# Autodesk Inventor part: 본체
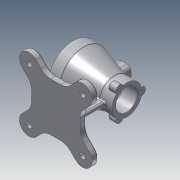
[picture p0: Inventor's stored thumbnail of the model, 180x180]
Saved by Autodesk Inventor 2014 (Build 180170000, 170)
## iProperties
Created: 2018-03
Part Number: 본체
Material: 알루미늄 6061
Document SubType Name: Modeling
Designer: net
Density: 2.71 g/cm^3
Appearance: 알루미늄 - 평지
Mass: 1015 g
Surface Area: 853.881 cm^2
Volume: 374.54 cm^3
Author: net
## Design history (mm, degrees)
sketch "스케치1"
  geometry: L1 (0, 0)-(0, 45); L2 (0, 45)-(20, 45); L3 (0, 0)-(100, 0); L4 (100, 0)-(100, 27.5); L5 (100, 27.5)-(77, 27.5); L6 (20, 45)-(77, 27.5)
  constraints: 12 end point, 2 perpendicular, 1 parallel, 1 vertical
  dimensions: "d0" = 45 distance of L1.start L1.end; "d1" = 20 distance of L1.end L2.end; "d3" = 100 distance of L1.start L3.end; "d4" = 27.5 distance of L3.end L4.end; "d5" = 23 distance of L4.end L5.end
revolve "회전1" sketch "스케치1" stored, may be unused: angle "d6" = 90 deg
sketch "스케치5"
  geometry: L1 (0, 0)-(50, 0); L2 (50, 0)-(50, 45); L3 (50, 45)-(62.5, 45); L4 (62.5, 45)-(62.5, 20); L5 (62.5, 20)-(50, 20); L6 (50, 20)-(50, 45); L7 (62.5, 20)-(37.5, 20); L8 (37.5, 20)-(37.5, 45); L9 (37.5, 45)-(62.5, 45); L10 (62.5, 45)-(62.5, 20)
  constraints: 20 end point, 4 parallel, 3 horizontal, 3 perpendicular
  dimensions: "d16" = 50 distance of L1.start L1.end; "d17" = 45 distance of L1.end L2.end; "d20" = 12.5 distance of L4.end L5.end; "d21" = 25 distance of L3.end L4.end; "d22" = 25 distance of L8.end L9.end
extrude "돌출4" join sketch "스케치5" stored distance "d23" = 25; taper "d24" = 0 deg
sketch "스케치2"
  geometry: C1 r 45 at (0, 0) reference; C2 r 35 at (0, 0)
  constraints: 1 centre point, 1 coincident
  dimensions: "d7" = 35 radius of C2
extrude "돌출1" cut sketch "스케치2" distance "d8" = 23; taper "d9" = 0 deg
sketch "스케치3"
  geometry: C1 r 35 at (0, 0) reference; C2 r 26 at (0, 0)
  constraints: 1 centre point, 1 coincident
  dimensions: "d10" = 26 radius of C2
extrude "돌출2" cut sketch "스케치3" distance "d11" = 47; taper "d12" = 0 deg
sketch "스케치4"
  geometry: C1 r 27.5 at (0, 0) reference; C2 r 20 at (0, 0)
  constraints: 1 centre point, 1 coincident
  dimensions: "d13" = 20 radius of C2
extrude "돌출3" cut sketch "스케치4" distance "d14" = 30; taper "d15" = 0 deg
sketch "스케치6"
  geometry: L1 (0, 25)-(25, 25); L2 (25, 25)-(25, 0); L3 (25, 0)-(0, 0); L4 (0, 0)-(0, 25); L5 (12.5, 12.5)-(20, 12.5); L6 (20, 12.5)-(20, 20); L7 (20, 20)-(12.5, 20); L8 (12.5, 20)-(12.5, 12.5); L9 (20, 20)-(5, 20); L10 (5, 20)-(5, 5); L11 (5, 5)-(20, 5); L12 (20, 5)-(20, 20); 1 further point
  constraints: 24 end point, 6 parallel, 3 horizontal, 3 perpendicular
  dimensions: "d25" = 7.5 distance of L7.end L6.end; "d26" = 7.5 distance of L6.end L5.end; "d27" = 15 distance of L11.end L10.end; "d28" = 15 distance of L10.end L9.end
extrude "돌출5" cut sketch "스케치6" distance "d29" = 30; taper "d30" = 0 deg
sketch "스케치7"
  geometry: L1 (0, 0)-(68.836, -39.743); L2 (0, 0)-(79.485, 0); L3 (0, 0)-(-52.99, -30.594); L4 (0, 0)-(61.188, 0); C1 r 7 at (0, 27.5); C2 r 20 at (0, 0) reference; 1 further point
  constraints: 8 end point, 2 equal length, 2 horizontal, 1 centre point, 1 vertical alignment, 1 other
  dimensions: "d31" = 7 radius of C1; "d116" = 30 deg angle of L1 L2; "d117" = 150 deg angle of L3 L4
extrude "돌출6" join sketch "스케치7" distance "d32" = 15; taper "d33" = 0 deg
sketch "스케치8"
  geometry: A1 r 7 centre (0, 0) between (6.943, -0.891) and (-6.943, -0.891) reference; A2 r 7 centre (-23.816, -41.25) between (-26.516, -34.792) and (-19.573, -46.817) reference; A3 r 7 centre (23.816, -41.25) between (19.573, -46.817) and (26.516, -34.792) reference; 3 further points
  constraints: 3 coincident
hole "구멍1" sketch "스케치8" at (0, 0), (-23.816, -41.25), (23.816, -41.25) diameter "d37" = 3.242; stored, may be unused: countersink angle "d41" = 90 deg, drill point angle "d43" = 118 deg; dims "d38" = 9, "d39" = 4, "d40" = 2, "d42" = 11
node "작업 평면1"
sketch "스케치10"
  geometry: L1 (-42.5, -7.5)-(-42.5, 7.5) reference; L2 (-42.5, 7.5)-(-57.5, 7.5) reference; L3 (-57.5, 7.5)-(-57.5, -7.5) reference; L4 (-57.5, -7.5)-(-42.5, -7.5) reference; L5 (-70, 26)-(-70, -26) reference; L6 (-23, 26)-(-23, -26) reference; L7 (-50, 0)-(-46, 0); L8 (-46, 0)-(-46, 24); L9 (-46, 24)-(-50, 24); L10 (-50, 24)-(-50, 0); L11 (-46, 24)-(-54, 24); L12 (-54, 24)-(-54, -24); L13 (-54, -24)-(-46, -24); L14 (-46, -24)-(-46, 24); 1 further point
  constraints: 16 end point, 4 parallel, 2 horizontal, 2 perpendicular
  dimensions: "d45" = 4 distance of L9.end L8.end; "d46" = 24 distance of L8.end L7.end; "d47" = 8 distance of L13.end L12.end; "d48" = 48 distance of L12.end L11.end
extrude "돌출7" join sketch "스케치10" stored distance "d49" = 15; taper "d50" = 0 deg
sketch "스케치11"
  geometry: L1 (95, 0)-(95, 45); L2 (95, 45)-(50, 45); L3 (95, 45)-(5, 45); L4 (5, 45)-(5, -45); L5 (5, -45)-(95, -45); L6 (95, -45)-(95, 45); 1 further point
  constraints: 12 end point, 2 parallel, 1 horizontal, 1 perpendicular
  dimensions: "d51" = 45 distance of L2.end L1.end; "d52" = 45 distance of L1.end L1.start; "d53" = 90 distance of L5.end L4.end; "d54" = 90 distance of L4.end L3.end
extrude "돌출8" join sketch "스케치11" distance "d55" = 12; taper "d56" = 0 deg
sketch "스케치12"
  geometry: L1 (50, 0)-(99.497, 49.497); L2 (50, 0)-(120, 0); L3 (50, 0)-(0.503, -49.497); L4 (50, 0)-(99.497, -49.497); L5 (50, 0)-(0.503, 49.497); L6 (-12.225, 36.77)-(86.77, -62.225); L7 (13.23, 62.225)-(112.225, -36.77); L8 (86.77, 62.225)-(-12.225, -36.77); L9 (112.225, 36.77)-(13.23, -62.225); A1 r 18 centre (99.497, 49.497) between (86.77, 62.225) and (112.225, 36.77); A2 r 18 centre (0.503, -49.497) between (-12.225, -36.77) and (13.23, -62.225); A3 r 18 centre (99.497, -49.497) between (86.77, -62.225) and (112.225, -36.77); A4 r 18 centre (0.503, 49.497) between (-12.225, 36.77) and (13.23, 62.225); 1 further point
  constraints: 18 end point, 8 point on circle, 6 tangent, 5 coincident, 4 centre point, 4 equal length, 1 horizontal, 1 perpendicular
  dimensions: "d57" = 70 distance of L1.start L1.end; "d58" = 45 deg angle of L2 L1; "d59" = 18 radius of A1; "d60" = 18 radius of A2; "d61" = 18 radius of A3; "d62" = 18 radius of A4
extrude "돌출9" join sketch "스케치12" distance "d63" = 12; taper "d64" = 0 deg
sketch "스케치13"
  geometry: C1 r 5 at (0.503, 49.497); C2 r 5 at (99.497, 49.497); C3 r 5 at (99.497, -49.497); C4 r 5 at (0.503, -49.497); A1 r 18 centre (0.503, -49.497) between (-12.225, -36.77) and (13.23, -62.225) reference; A2 r 18 centre (99.497, -49.497) between (86.77, -62.225) and (112.225, -36.77) reference; A3 r 18 centre (99.497, 49.497) between (112.225, 36.77) and (86.77, 62.225) reference; A4 r 18 centre (0.503, 49.497) between (13.23, 62.225) and (-12.225, 36.77) reference; 1 further point
  constraints: 4 centre point, 4 coincident
  dimensions: "d65" = 5 radius of C1; "d66" = 5 radius of C2; "d67" = 5 radius of C3; "d68" = 5 radius of C4
extrude "돌출10" cut sketch "스케치13" distance "d69" = 12; taper "d70" = 0 deg
feature "면 기울기2" dims angle "d113" = 5 deg
feature "면 기울기3" dims angle "d114" = 5 deg
sketch "스케치14"
  geometry: L1 (69.544, 45)-(30.456, 45) reference; L2 (50, 0)-(13, 0); L3 (13, 0)-(87, 0); L4 (13, 0)-(87, 0); L5 (87, 0)-(87, 4); L6 (87, 4)-(13, 4); L7 (13, 4)-(13, 0); L8 (13, 4)-(87, 4); L9 (87, 4)-(87, -4); L10 (87, -4)-(13, -4); L11 (13, -4)-(13, 4); 1 further point
  constraints: 20 end point, 5 parallel, 2 horizontal, 2 perpendicular, 1 collinear
  dimensions: "d71" = 37 distance of L2.start L2.end; "d72" = 74 distance of L2.end L3.end; "d73" = 4 distance of L5.end L4.end; "d74" = 8 distance of L8.end L9.end
extrude "돌출11" join sketch "스케치14" stored distance "d75" = 12; taper "d76" = 0 deg
sketch "스케치15" dims "d77" = 40
  geometry: C1 r 45 at (0, 0) reference; 2 further points
  constraints: 1 coincident, 1 vertical alignment, 2 other
hole "구멍2" sketch "스케치15" at (0, 40) diameter "d78" = 3.242; stored, may be unused: countersink angle "d82" = 90 deg, drill point angle "d84" = 118 deg; dims "d79" = 9, "d80" = 4, "d81" = 2, "d83" = 11
fillet "모깎기1" dims "d88" = 3
chamfer "모따기1" distance "d89" = 1; stored, may be unused: second distance "d90" = 2, angle "d91" = 45 deg
fillet "모깎기2" dims "d92" = 3
fillet "모깎기3" dims "d93" = 3
fillet "모깎기4" dims "d94" = 3
fillet "모깎기6" dims "d96" = 3
fillet "모깎기7" dims "d97" = 8
fillet "모깎기8" dims "d98" = 3
fillet "모깎기9" dims "d99" = 1
fillet "모깎기12" dims "d115" = 25
chamfer "모따기2" distance "d100" = 3; stored, may be unused: second distance "d101" = 2, angle "d102" = 45 deg
fillet "모깎기10" dims "d103" = 1
fillet "모깎기11" dims "d104" = 3
sketch "스케치16"
  geometry: L1 (92, 9.189)-(92, -9.189) reference; L2 (50, 0)-(50, -35); L3 (95, -9.189)-(95, 9.189) reference; L4 (95, 0)-(50, 0); 6 further points
  constraints: 4 end point, 1 coincident, 1 midpoint, 1 parallel, 1 perpendicular, 1 other
  dimensions: "d105" = 35 distance of L2.start L2.end; "d106" = 45 distance of L4.start L2.start
feature "엠보싱1" sketch "스케치16" dims "d0" = 45, "d1" = 20, "d3" = 100, "d4" = 27.5, "d5" = 23, "d107" = 0.5, "d108" = 0
chamfer "모따기3" distance "d109" = 1; stored, may be unused: second distance "d110" = 2, angle "d111" = 45 deg
node "솔리드1"
pattern_circular "원형 패턴1" dims angle "d35" = 360 deg
pattern_circular "원형 패턴2" dims angle "d86" = 360 deg
node "투영된 루프1"
other parameters: "d44" = -82
